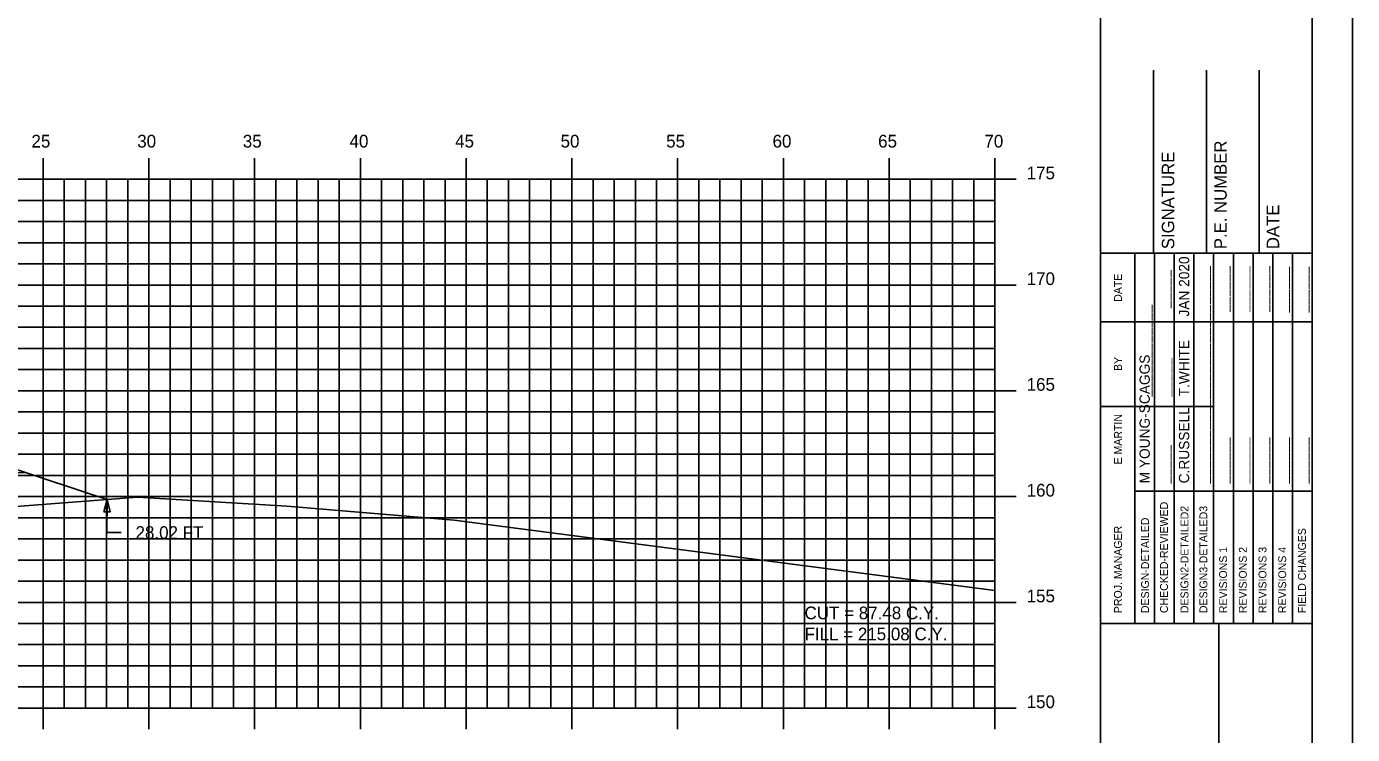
# Model space of a CAD drawing. Extents: x 1141424 to 1141594, y 608981 to 609091.
# Drawn here: x 1141531.5 to 1141594.2, y 609024.1 to 609057.6 of the extents above; entities that cross this region are included whole.
import ezdxf

# ---------------------------------------------------------------- set-up
doc = ezdxf.new("R2010")
doc.units = 0
for name, color, linetype in [('BORDER', 7, 'Continuous'), ('D_Roadway_SlopeLines', 7, 'Continuous'), ('D_Roadway_SubGrade', 7, 'Continuous'), ('D_Text_Standard', 7, 'Continuous'), ('H_V ANNOTATION', 7, 'Continuous'), ('MAJOR', 7, 'Continuous'), ('MINOR', 7, 'Continuous'), ('PLOT BOUNDARY', 7, 'Continuous'), ('S_Roadway_Centerline', 7, 'Continuous')]:
    doc.layers.add(name, color=color, linetype=linetype)

msp = doc.modelspace()

# ---------------------------------------------------------------- linework, layer by layer
msp.add_lwpolyline([(1141463.072, 609043.268), (1141478.738, 609035.436), (1141481.738, 609036.436), (1141489.27, 609038.946), (1141489.271, 609038.946), (1141496.271, 609039.226), (1141507.271, 609039.446), (1141518.271, 609039.226), (1141523.862, 609039.003), (1141531.484, 609036.462), (1141534.484, 609035.462), (1141535.293, 609035.192)])
at = {"layer": 'BORDER'}
for p, q in [((1141582.271, 608984.335), (1141582.271, 609089.335)), ((1141584.771, 609046.838), (1141584.771, 609055.485)), ((1141587.271, 609046.838), (1141587.271, 609055.485)), ((1141589.771, 609046.838), (1141589.771, 609055.485)), ((1141582.271, 609046.838), (1141592.271, 609046.838)), ((1141582.271, 609029.338), (1141592.271, 609029.338)), ((1141587.862, 608994.338), (1141587.862, 609029.338))]:
    msp.add_line(p, q, dxfattribs=at)
msp.add_lwpolyline([(1141432.271, 608984.335), (1141592.271, 608984.335), (1141592.271, 609089.335), (1141432.271, 609089.335)], close=True, dxfattribs=at)
for points in [[(1141583.886, 609043.588), (1141583.886, 609046.838)], [(1141584.818, 609029.341), (1141584.818, 609046.838)], [(1141585.75, 609046.838), (1141585.75, 609029.341)], [(1141586.682, 609029.341), (1141586.682, 609046.838)], [(1141587.613, 609029.341), (1141587.613, 609046.838)], [(1141588.545, 609029.341), (1141588.545, 609046.838)], [(1141589.477, 609029.341), (1141589.477, 609046.838)], [(1141590.408, 609029.341), (1141590.408, 609046.838)], [(1141591.34, 609029.341), (1141591.34, 609046.838)], [(1141583.887, 609029.341), (1141583.887, 609046.132)], [(1141582.271, 609043.588), (1141592.271, 609043.588)], [(1141582.271, 609039.588), (1141583.887, 609039.588)], [(1141583.886, 609039.588), (1141587.612, 609039.588)], [(1141583.886, 609035.588), (1141592.271, 609035.588)]]:
    msp.add_lwpolyline(points, dxfattribs=at)
at = {"layer": 'D_Roadway_SlopeLines'}
for points in [[(1141531.484, 609036.462), (1141534.484, 609035.462)], [(1141534.484, 609035.462), (1141535.293, 609035.192)]]:
    msp.add_lwpolyline(points, dxfattribs=at)
at = {"layer": 'D_Roadway_SubGrade'}
msp.add_lwpolyline([(1141518.271, 609038.81), (1141518.271, 609038.976), (1141523.862, 609038.753), (1141523.862, 609039.003), (1141523.862, 609039.003), (1141531.484, 609036.462), (1141518.271, 609036.726)], close=True, dxfattribs=at)
at = {"layer": 'D_Text_Standard'}
msp.add_lwpolyline([(1141535.293, 609035.192), (1141535.433, 609034.609), (1141535.142, 609034.612)], close=True, dxfattribs=at)
msp.add_lwpolyline([(1141535.293, 609035.192), (1141535.279, 609033.634), (1141535.959, 609033.634)], dxfattribs=at)
at = {"layer": 'MAJOR'}
for p, q in [((1141532.271, 609051.337), (1141532.271, 609050.335)), ((1141537.271, 609051.337), (1141537.271, 609050.335)), ((1141542.271, 609051.337), (1141542.271, 609050.335)), ((1141547.271, 609051.337), (1141547.271, 609050.335)), ((1141552.271, 609051.337), (1141552.271, 609050.335)), ((1141557.271, 609051.337), (1141557.271, 609050.335)), ((1141562.271, 609051.337), (1141562.271, 609050.335)), ((1141567.271, 609051.337), (1141567.271, 609050.335)), ((1141572.271, 609051.337), (1141572.271, 609050.335)), ((1141577.271, 609051.337), (1141577.271, 609050.335)), ((1141437.271, 609050.335), (1141577.271, 609050.335)), ((1141437.271, 609050.335), (1141577.271, 609050.335)), ((1141532.271, 609025.335), (1141532.271, 609050.335)), ((1141537.271, 609025.335), (1141537.271, 609050.335)), ((1141542.271, 609025.335), (1141542.271, 609050.335)), ((1141547.271, 609025.335), (1141547.271, 609050.335)), ((1141552.271, 609025.335), (1141552.271, 609050.335)), ((1141557.271, 609025.335), (1141557.271, 609050.335)), ((1141562.271, 609025.335), (1141562.271, 609050.335)), ((1141567.271, 609025.335), (1141567.271, 609050.335)), ((1141572.271, 609025.335), (1141572.271, 609050.335)), ((1141578.273, 609050.335), (1141576.269, 609050.335)), ((1141577.271, 609025.335), (1141577.271, 609050.335)), ((1141577.271, 609025.335), (1141577.271, 609050.335)), ((1141437.271, 609045.335), (1141577.271, 609045.335)), ((1141578.273, 609045.335), (1141576.269, 609045.335)), ((1141437.271, 609040.335), (1141577.271, 609040.335)), ((1141578.273, 609040.335), (1141576.269, 609040.335)), ((1141437.271, 609035.335), (1141577.271, 609035.335)), ((1141578.273, 609035.335), (1141576.269, 609035.335)), ((1141437.271, 609030.335), (1141577.271, 609030.335)), ((1141578.273, 609030.335), (1141576.269, 609030.335)), ((1141437.271, 609025.335), (1141577.271, 609025.335)), ((1141437.271, 609025.335), (1141577.271, 609025.335)), ((1141532.271, 609024.333), (1141532.271, 609025.335)), ((1141537.271, 609024.333), (1141537.271, 609025.335)), ((1141542.271, 609024.333), (1141542.271, 609025.335)), ((1141547.271, 609024.333), (1141547.271, 609025.335)), ((1141552.271, 609024.333), (1141552.271, 609025.335)), ((1141557.271, 609024.333), (1141557.271, 609025.335)), ((1141562.271, 609024.333), (1141562.271, 609025.335)), ((1141567.271, 609024.333), (1141567.271, 609025.335)), ((1141572.271, 609024.333), (1141572.271, 609025.335)), ((1141578.273, 609025.335), (1141576.269, 609025.335)), ((1141577.271, 609024.333), (1141577.271, 609025.335))]:
    msp.add_line(p, q, dxfattribs=at)
at = {"layer": 'MINOR'}
for p, q in [((1141533.271, 609025.335), (1141533.271, 609050.335)), ((1141534.271, 609025.335), (1141534.271, 609050.335)), ((1141535.271, 609025.335), (1141535.271, 609050.335)), ((1141536.271, 609025.335), (1141536.271, 609050.335)), ((1141538.271, 609025.335), (1141538.271, 609050.335)), ((1141539.271, 609025.335), (1141539.271, 609050.335)), ((1141540.271, 609025.335), (1141540.271, 609050.335)), ((1141541.271, 609025.335), (1141541.271, 609050.335)), ((1141543.271, 609025.335), (1141543.271, 609050.335)), ((1141544.271, 609025.335), (1141544.271, 609050.335)), ((1141545.271, 609025.335), (1141545.271, 609050.335)), ((1141546.271, 609025.335), (1141546.271, 609050.335)), ((1141548.271, 609025.335), (1141548.271, 609050.335)), ((1141549.271, 609025.335), (1141549.271, 609050.335)), ((1141550.271, 609025.335), (1141550.271, 609050.335)), ((1141551.271, 609025.335), (1141551.271, 609050.335)), ((1141553.271, 609025.335), (1141553.271, 609050.335)), ((1141554.271, 609025.335), (1141554.271, 609050.335)), ((1141555.271, 609025.335), (1141555.271, 609050.335)), ((1141556.271, 609025.335), (1141556.271, 609050.335)), ((1141558.271, 609025.335), (1141558.271, 609050.335)), ((1141559.271, 609025.335), (1141559.271, 609050.335)), ((1141560.271, 609025.335), (1141560.271, 609050.335)), ((1141561.271, 609025.335), (1141561.271, 609050.335)), ((1141563.271, 609025.335), (1141563.271, 609050.335)), ((1141564.271, 609025.335), (1141564.271, 609050.335)), ((1141565.271, 609025.335), (1141565.271, 609050.335)), ((1141566.271, 609025.335), (1141566.271, 609050.335)), ((1141568.271, 609025.335), (1141568.271, 609050.335)), ((1141569.271, 609025.335), (1141569.271, 609050.335)), ((1141570.271, 609025.335), (1141570.271, 609050.335)), ((1141571.271, 609025.335), (1141571.271, 609050.335)), ((1141573.271, 609025.335), (1141573.271, 609050.335)), ((1141574.271, 609025.335), (1141574.271, 609050.335)), ((1141575.271, 609025.335), (1141575.271, 609050.335)), ((1141576.271, 609025.335), (1141576.271, 609050.335)), ((1141437.271, 609049.335), (1141577.271, 609049.335)), ((1141577.271, 609049.335), (1141576.269, 609049.335)), ((1141437.271, 609048.335), (1141577.271, 609048.335)), ((1141577.271, 609048.335), (1141576.269, 609048.335)), ((1141437.271, 609047.335), (1141577.271, 609047.335)), ((1141577.271, 609047.335), (1141576.269, 609047.335)), ((1141437.271, 609046.335), (1141577.271, 609046.335)), ((1141577.271, 609046.335), (1141576.269, 609046.335)), ((1141437.271, 609044.335), (1141577.271, 609044.335)), ((1141577.271, 609044.335), (1141576.269, 609044.335)), ((1141437.271, 609043.335), (1141577.271, 609043.335)), ((1141577.271, 609043.335), (1141576.269, 609043.335)), ((1141437.271, 609042.335), (1141577.271, 609042.335)), ((1141577.271, 609042.335), (1141576.269, 609042.335)), ((1141437.271, 609041.335), (1141577.271, 609041.335)), ((1141577.271, 609041.335), (1141576.269, 609041.335)), ((1141437.271, 609039.335), (1141577.271, 609039.335)), ((1141577.271, 609039.335), (1141576.269, 609039.335)), ((1141437.271, 609038.335), (1141577.271, 609038.335)), ((1141577.271, 609038.335), (1141576.269, 609038.335)), ((1141437.271, 609037.335), (1141577.271, 609037.335)), ((1141577.271, 609037.335), (1141576.269, 609037.335)), ((1141437.271, 609036.335), (1141577.271, 609036.335)), ((1141577.271, 609036.335), (1141576.269, 609036.335)), ((1141437.271, 609034.335), (1141577.271, 609034.335)), ((1141577.271, 609034.335), (1141576.269, 609034.335)), ((1141437.271, 609033.335), (1141577.271, 609033.335)), ((1141577.271, 609033.335), (1141576.269, 609033.335)), ((1141437.271, 609032.335), (1141577.271, 609032.335)), ((1141577.271, 609032.335), (1141576.269, 609032.335)), ((1141437.271, 609031.335), (1141577.271, 609031.335)), ((1141577.271, 609031.335), (1141576.269, 609031.335)), ((1141437.271, 609029.335), (1141577.271, 609029.335)), ((1141577.271, 609029.335), (1141576.269, 609029.335)), ((1141437.271, 609028.335), (1141577.271, 609028.335)), ((1141577.271, 609028.335), (1141576.269, 609028.335)), ((1141437.271, 609027.335), (1141577.271, 609027.335)), ((1141577.271, 609027.335), (1141576.269, 609027.335)), ((1141437.271, 609026.335), (1141577.271, 609026.335)), ((1141577.271, 609026.335), (1141576.269, 609026.335))]:
    msp.add_line(p, q, dxfattribs=at)
at = {"layer": 'PLOT BOUNDARY'}
msp.add_lwpolyline([(1141424.178, 608981.276), (1141594.178, 608981.276), (1141594.178, 609091.276), (1141424.178, 609091.276)], close=True, dxfattribs=at)
at = {"layer": 'S_Roadway_Centerline'}
msp.add_lwpolyline([(1141460.253, 609043.541), (1141476.77, 609041.777), (1141482.141, 609040.888), (1141491.527, 609035.647), (1141491.862, 609035.413), (1141494.612, 609035.718), (1141494.678, 609035.735), (1141496.776, 609036.013), (1141497.432, 609036.106), (1141508.706, 609036.443), (1141508.794, 609036.445), (1141517.825, 609036.227), (1141519.734, 609036.183), (1141519.739, 609036.182), (1141523.102, 609035.791), (1141523.112, 609035.787), (1141526.932, 609034.675), (1141527.029, 609034.645), (1141527.286, 609034.589), (1141536.73, 609035.3), (1141543.797, 609034.883), (1141551.696, 609034.212), (1141577.271, 609030.888)], dxfattribs=at)

# ---------------------------------------------------------------- texts
at = {"layer": 'BORDER'}
for s, height, p in [('P.E. NUMBER', 0.59055, (1141588.232, 609047.03)), ('SIGNATURE', 0.5906, (1141585.751, 609047.03)), ('DATE', 0.5906, (1141590.712, 609047.03)), ('JAN 2020', 0.4845, (1141586.457, 609043.843)), ('DATE', 0.3714, (1141583.275, 609044.544)), ('_____', 0.4845, (1141585.488, 609044.243)), ('______', 0.4845, (1141587.352, 609044.063)), ('______', 0.4845, (1141588.283, 609044.065)), ('______', 0.4845, (1141589.215, 609044.067)), ('______', 0.4845, (1141590.147, 609044.067)), ('______', 0.4845, (1141591.078, 609044.036)), ('______', 0.4845, (1141592.01, 609044.036)), ('____________', 0.48455, (1141584.594, 609040.073)), ('____________', 0.48455, (1141587.352, 609040.073)), ('T.WHITE', 0.4845, (1141586.457, 609040.073)), ('M YOUNG-SCAGGS', 0.48455, (1141584.594, 609035.961)), ('BY', 0.3714, (1141583.275, 609041.273)), ('_____', 0.4845, (1141585.526, 609040.073)), ('____________', 0.48455, (1141587.352, 609035.961)), ('C.RUSSELL', 0.4845, (1141586.457, 609035.961)), ('E MARTIN', 0.3727, (1141583.275, 609036.855)), ('_____', 0.4845, (1141585.488, 609035.961)), ('______', 0.4845, (1141588.283, 609035.961)), ('______', 0.4845, (1141589.215, 609035.961)), ('______', 0.4845, (1141590.147, 609035.961)), ('______', 0.4845, (1141591.078, 609035.961)), ('______', 0.4845, (1141592.01, 609035.961)), ('CHECKED-REVIEWED', 0.37275, (1141585.452, 609029.826)), ('DESIGN2-DETAILED2', 0.37275, (1141586.421, 609029.826)), ('DESIGN3-DETAILED3', 0.37275, (1141587.315, 609029.826)), ('PROJ. MANAGER', 0.37275, (1141583.275, 609029.826)), ('DESIGN-DETAILED', 0.37275, (1141584.557, 609029.826)), ('FIELD CHANGES', 0.37275, (1141591.974, 609029.826)), ('REVISIONS 1', 0.37275, (1141588.247, 609029.826)), ('REVISIONS 2', 0.37275, (1141589.179, 609029.826)), ('REVISIONS 3', 0.37275, (1141590.11, 609029.826)), ('REVISIONS 4', 0.37275, (1141591.042, 609029.826))]:
    msp.add_text(s, height=height, rotation=90, dxfattribs=at).set_placement(p)
at = {"layer": 'D_Text_Standard'}
for s, p in [('28.02 FT', (1141536.638, 609033.334)), ('CUT = 87.48 C.Y.', (1141568.271, 609029.535)), ('FILL = 215.08 C.Y.', (1141568.271, 609028.539))]:
    msp.add_text(s, height=0.6, dxfattribs=at).set_placement(p)
at = {"layer": 'H_V ANNOTATION'}
for s, p in [('25', (1141531.717, 609051.835)), ('30', (1141536.719, 609051.835)), ('35', (1141541.711, 609051.835)), ('40', (1141546.757, 609051.835)), ('45', (1141551.749, 609051.835)), ('50', (1141556.735, 609051.835)), ('55', (1141561.727, 609051.835)), ('60', (1141566.757, 609051.835)), ('65', (1141571.749, 609051.835)), ('70', (1141576.773, 609051.835)), ('175', (1141578.771, 609050.335)), ('170', (1141578.771, 609045.335)), ('165', (1141578.771, 609040.335)), ('160', (1141578.771, 609035.335)), ('155', (1141578.771, 609030.335)), ('150', (1141578.771, 609025.335))]:
    msp.add_text(s, height=0.6, dxfattribs=at).set_placement(p)

doc.saveas('drawing.dxf')
